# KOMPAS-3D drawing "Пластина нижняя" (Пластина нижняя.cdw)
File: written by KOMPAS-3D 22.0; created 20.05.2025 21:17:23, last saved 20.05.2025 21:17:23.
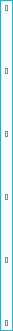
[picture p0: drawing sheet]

Sheet 1: A4, portrait

Document properties: Автор: user; Масса: 26.939167; Полное имя файла: ..\Пластина нижняя.m3d

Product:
- Part/product: Пластина нижняя
    Масса: 26.939167

Title block, sheet 1: Наименование: Пластина нижняя; Материал: Сталь 10 ГОСТ 1050-2013; Масса: 26,94; Количество листов документа: 1; Форматы листов документа: A4

Views: Вид 1, Сверху
Referenced files in D:\Работа\2025\5. Май\Задание №6 - Тележка для крыши\3Д\Тележка в сборе\: Пластина нижняя.m3d
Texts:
  Без оформления
Dimensions and other numbers on the sheet: 7; 1:1; 1; 26,94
